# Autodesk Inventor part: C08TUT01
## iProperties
Created: 2009-04
Part Number: C08TUT01
Document SubType Name: Modeling
Designer: Sham
Density: 1 g/cm^3
Author: Sham
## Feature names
1. Sweep2
2. Shell2
3. Extrusion2
4. Extrusion3
5. Hole1
6. Circular Pattern1
7. Hole2
8. Circular Pattern2
9. Extrusion4
10. Fillet1
11. Hole4
12. Extrusion5
13. Hole5
